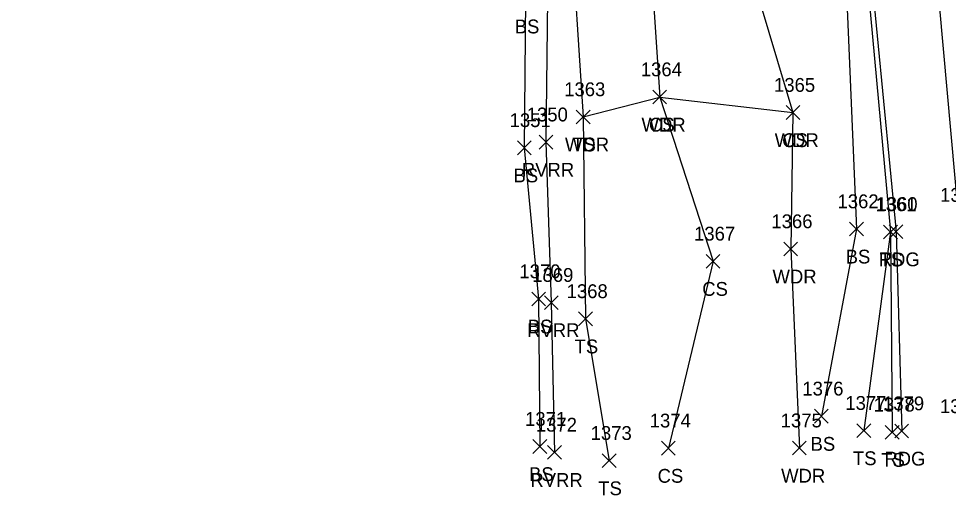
# Model space of a CAD drawing. Extents: x 1469310 to 1475157, y 493997 to 498873.
# Drawn here: x 1469498.4 to 1469633, y 498324.4 to 498393.4 of the extents above; entities that cross this region are included whole.
import ezdxf

# ---------------------------------------------------------------- set-up
doc = ezdxf.new("R2010")
doc.units = 0
for name, color, linetype in [('L_A', 7, 'Continuous'), ('L_I', 7, 'Continuous'), ('L_TIC', 7, 'Continuous'), ('LAWA', 7, 'Continuous'), ('LAWE', 7, 'Continuous'), ('LELB', 7, 'Continuous'), ('P_A', 7, 'Continuous'), ('P_I', 7, 'Continuous'), ('P_TIC', 7, 'Continuous'), ('PEU', 7, 'Continuous'), ('PRC', 7, 'Continuous')]:
    doc.layers.add(name, color=color, linetype=linetype)

msp = doc.modelspace()

# ---------------------------------------------------------------- linework, layer by layer
at = {"layer": 'L_TIC'}
for points in [[(1469590.18, 498381.07), (1469592.18, 498383.07)], [(1469592.18, 498381.07), (1469590.18, 498383.07)], [(1469590.18, 498381.07), (1469592.18, 498383.07)], [(1469592.18, 498381.07), (1469590.18, 498383.07)], [(1469609.46, 498378.82), (1469611.46, 498380.82)], [(1469611.46, 498378.82), (1469609.46, 498380.82)], [(1469609.46, 498378.82), (1469611.46, 498380.82)], [(1469611.46, 498378.82), (1469609.46, 498380.82)], [(1469579.09, 498378.19), (1469581.09, 498380.19)], [(1469581.09, 498378.19), (1469579.09, 498380.19)], [(1469579.09, 498378.19), (1469581.09, 498380.19)], [(1469581.09, 498378.19), (1469579.09, 498380.19)], [(1469570.57, 498373.72), (1469572.57, 498375.72)], [(1469572.57, 498373.72), (1469570.57, 498375.72)], [(1469573.71, 498374.54), (1469575.71, 498376.54)], [(1469575.71, 498374.54), (1469573.71, 498376.54)], [(1469618.65, 498361.97), (1469620.65, 498363.97)], [(1469620.65, 498361.97), (1469618.65, 498363.97)], [(1469623.57, 498361.54), (1469625.57, 498363.54)], [(1469625.57, 498361.54), (1469623.57, 498363.54)], [(1469623.57, 498361.54), (1469625.57, 498363.54)], [(1469625.57, 498361.54), (1469623.57, 498363.54)], [(1469609.13, 498359.08), (1469611.13, 498361.08)], [(1469611.13, 498359.08), (1469609.13, 498361.08)], [(1469597.89, 498357.29), (1469599.89, 498359.29)], [(1469599.89, 498357.29), (1469597.89, 498359.29)], [(1469572.65, 498351.84), (1469574.65, 498353.84)], [(1469574.65, 498351.84), (1469572.65, 498353.84)], [(1469574.48, 498351.31), (1469576.48, 498353.31)], [(1469576.48, 498351.31), (1469574.48, 498353.31)], [(1469579.44, 498348.96), (1469581.44, 498350.96)], [(1469581.44, 498348.96), (1469579.44, 498350.96)], [(1469613.57, 498334.86), (1469615.57, 498336.86)], [(1469615.57, 498334.86), (1469613.57, 498336.86)], [(1469619.73, 498332.78), (1469621.73, 498334.78)], [(1469621.73, 498332.78), (1469619.73, 498334.78)], [(1469623.83, 498332.54), (1469625.83, 498334.54)], [(1469625.83, 498332.54), (1469623.83, 498334.54)], [(1469572.82, 498330.47), (1469574.82, 498332.47)], [(1469574.82, 498330.47), (1469572.82, 498332.47)], [(1469610.39, 498330.25), (1469612.39, 498332.25)], [(1469612.39, 498330.25), (1469610.39, 498332.25)], [(1469574.94, 498329.63), (1469576.94, 498331.63)], [(1469576.94, 498329.63), (1469574.94, 498331.63)], [(1469591.43, 498330.23), (1469593.43, 498332.23)], [(1469593.43, 498330.23), (1469591.43, 498332.23)], [(1469582.87, 498328.43), (1469584.87, 498330.43)], [(1469584.87, 498328.43), (1469582.87, 498330.43)]]:
    msp.add_lwpolyline(points, dxfattribs=at)
at = {"layer": 'LAWA'}
msp.add_lwpolyline([(1469580.09, 498379.19), (1469591.18, 498382.07), (1469610.46, 498379.82), (1469610.13, 498360.08), (1469611.39, 498331.25)], dxfattribs=at)
at = {"layer": 'LAWE'}
msp.add_lwpolyline([(1469541.73, 498555.03), (1469545.19, 498552.67), (1469541.67, 498546.71), (1469525.68, 498530.28), (1469522.4, 498516.01), (1469543.45, 498481.78), (1469558.18, 498452.24), (1469573.2, 498427.49), (1469574.96, 498400.53), (1469574.71, 498375.54), (1469575.48, 498352.31), (1469575.94, 498330.63)], dxfattribs=at)
at = {"layer": 'LELB'}
for points in [[(1469542.74, 498553.27), (1469541.61, 498548.4), (1469522.4, 498532.22), (1469522.16, 498514.95), (1469541.19, 498477.77), (1469556.44, 498450.64), (1469569.24, 498427.49), (1469571.75, 498396.28), (1469571.57, 498374.72), (1469573.65, 498352.84), (1469573.82, 498331.47)], [(1469583.84, 498494.95), (1469584.94, 498488.74), (1469602.02, 498459.07), (1469610.17, 498437.24), (1469617.9, 498405.01), (1469618.1, 498399.47), (1469619.65, 498362.97), (1469614.57, 498335.86)], [(1469591.51, 498490.22), (1469607.36, 498458.33), (1469613.96, 498438.31), (1469620.12, 498405.06), (1469621.11, 498400.23), (1469624.57, 498362.54), (1469624.83, 498333.54)], [(1469566.51, 498459.59), (1469581.31, 498438.71), (1469580.88, 498434.22), (1469578.88, 498431.59), (1469580.35, 498426.94), (1469583.12, 498414.68), (1469578.84, 498398.56), (1469580.09, 498379.19), (1469580.44, 498349.96), (1469583.87, 498329.43)], [(1469610.17, 498437.24), (1469610.54, 498405.04), (1469604.75, 498398.93), (1469610.46, 498379.82)], [(1469594.99, 498406.55), (1469590.04, 498399.48), (1469591.18, 498382.07), (1469598.89, 498358.29), (1469592.43, 498331.23)], [(1469624.57, 498362.54), (1469620.73, 498333.78)]]:
    msp.add_lwpolyline(points, dxfattribs=at)
at = {"layer": 'P_TIC'}
for points in [[(1469624.38, 498361.57), (1469626.38, 498363.57)], [(1469626.38, 498361.57), (1469624.38, 498363.57)], [(1469625.2, 498332.72), (1469627.2, 498334.72)], [(1469627.2, 498332.72), (1469625.2, 498334.72)]]:
    msp.add_lwpolyline(points, dxfattribs=at)
at = {"layer": 'PEU'}
msp.add_lwpolyline([(1469418.16, 498735.54), (1469447.91, 498704.22), (1469471.83, 498679.03), (1469509.9, 498637.99), (1469529.4, 498614.8), (1469545.14, 498594.13), (1469565.65, 498563.08), (1469576.41, 498543.24), (1469581.13, 498534.68), (1469591.75, 498510.08), (1469602.71, 498485.38), (1469609.03, 498458.44), (1469615.47, 498438.56), (1469621.98, 498404.81), (1469621.72, 498400.42), (1469625.38, 498362.57), (1469626.2, 498333.72)], dxfattribs=at)
at = {"layer": 'PRC'}
msp.add_lwpolyline([(1469423.49, 498741.59), (1469452.57, 498710.45), (1469477.96, 498685.46), (1469512.01, 498647.6), (1469532.7, 498623.32), (1469554.78, 498596.5), (1469570.66, 498571.79), (1469585.25, 498547.18), (1469603.31, 498509.95), (1469610.7, 498488.94), (1469623.7, 498439.14), (1469630.72, 498407.83), (1469631.04, 498401.91), (1469634.46, 498363.9), (1469634.52, 498333.31)], dxfattribs=at)

# ---------------------------------------------------------------- texts
at = {"layer": 'L_A'}
for s, p in [('BS', (1469570.19, 498391.28)), ('WDR', (1469588.54, 498377.07)), ('CS', (1469589.62, 498377.07)), ('WDR', (1469607.82, 498374.82)), ('CS', (1469608.9, 498374.82)), ('WDR', (1469577.46, 498374.19)), ('TS', (1469578.5, 498374.19)), ('BS', (1469570.01, 498369.72)), ('RVRR', (1469571.22, 498370.54)), ('BS', (1469618.09, 498357.97)), ('TS', (1469622.98, 498357.54)), ('TS', (1469622.98, 498357.54)), ('WDR', (1469607.5, 498355.08)), ('CS', (1469597.33, 498353.29)), ('BS', (1469572.09, 498347.84)), ('RVRR', (1469571.99, 498347.31)), ('TS', (1469578.85, 498344.96)), ('BS', (1469613.01, 498330.86)), ('TS', (1469619.14, 498328.78)), ('TS', (1469623.24, 498328.54)), ('BS', (1469572.26, 498326.47)), ('CS', (1469590.87, 498326.23)), ('WDR', (1469608.75, 498326.25)), ('RVRR', (1469572.45, 498325.63)), ('TS', (1469582.28, 498324.43))]:
    msp.add_text(s, height=2, dxfattribs=at).set_placement(p)
at = {"layer": 'L_I'}
for s, p in [('1364', (1469588.44, 498385.07)), ('1364', (1469588.44, 498385.07)), ('1365', (1469607.72, 498382.82)), ('1365', (1469607.72, 498382.82)), ('1363', (1469577.35, 498382.19)), ('1363', (1469577.35, 498382.19)), ('1351', (1469569.45, 498377.72)), ('1350', (1469571.93, 498378.54)), ('1362', (1469616.91, 498365.97)), ('1361', (1469622.4, 498365.54)), ('1361', (1469622.4, 498365.54)), ('1366', (1469607.34, 498363.08)), ('1367', (1469596.15, 498361.29)), ('1370', (1469570.87, 498355.84)), ('1369', (1469572.73, 498355.31)), ('1368', (1469577.7, 498352.96)), ('1376', (1469611.82, 498338.86)), ('1377', (1469618.04, 498336.78)), ('1378', (1469622.14, 498336.54)), ('1371', (1469571.69, 498334.47)), ('1375', (1469608.69, 498334.25)), ('1372', (1469573.25, 498333.63)), ('1374', (1469589.73, 498334.23)), ('1373', (1469581.18, 498332.43))]:
    msp.add_text(s, height=2, dxfattribs=at).set_placement(p)
at = {"layer": 'P_A'}
for p in [(1469622.87, 498357.57), (1469623.69, 498328.72)]:
    msp.add_text('RDG', height=2, dxfattribs=at).set_placement(p)
at = {"layer": 'P_I'}
for s, p in [('1359', (1469631.76, 498366.9)), ('1360', (1469622.55, 498365.57)), ('1379', (1469623.5, 498336.72)), ('1380', (1469631.74, 498336.31))]:
    msp.add_text(s, height=2, dxfattribs=at).set_placement(p)

doc.saveas('drawing.dxf')
